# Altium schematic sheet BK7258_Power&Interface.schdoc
size 261 x 208 mm
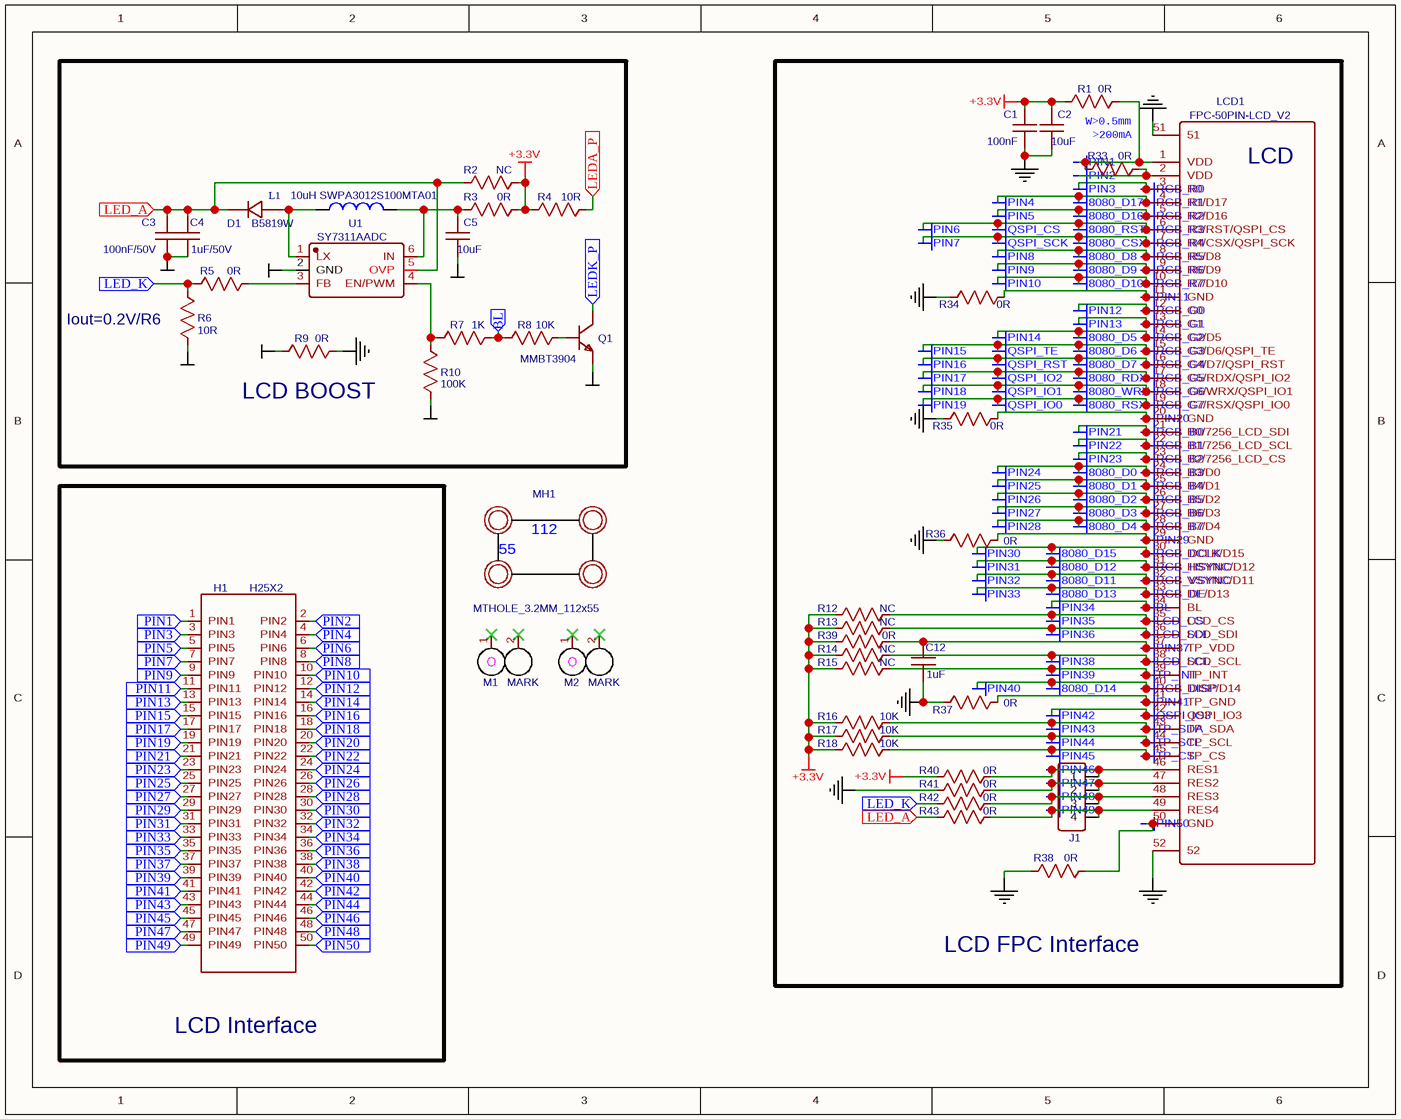
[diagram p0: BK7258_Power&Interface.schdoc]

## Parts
C1  100nF  [C0402]
C2  10uF  [C0603]
C3  100nF/50V  [C0603]
C4  1uF/50V  [C0603]
C5  10uF  [C0603]
C12  1uF  [C0402]
D1  B5819W  [SOD-123]
H1  H25X2  [H25X2]
J1  HDR-M-2.54_1x4  [HDR-M-2.54_1X4]  (value not drawn)
L1  10uH SWPA3012S100MTA01  [L3012]
LCD1  FPC-50PIN-LCD_V2  [FPC-SMD_AFC01-S50FCC-00_VERSA]
M1  MARK  [MARK]
M2  MARK  [MARK]
MH1  MTHOLE_3.2MM_112x55  [MTHOLE_3.2MM_112X55]
Q1  MMBT3904  [SOT-23]
R1  0R  [R0402]
R2  NC  [R0402]
R3  0R  [R0402]
R4  10R  [R0402]
R5  0R  [R0402]
R6  10R  [R0402]
R7  1K  [R0402]
R8  10K  [R0402]
R9  0R  [R0402]
R10  100K  [R0402]
R12  NC  [R0402]
R13  NC  [R0402]
R14  NC  [R0402]
R15  NC  [R0402]
R16  10K  [R0402]
R17  10K  [R0402]
R18  10K  [R0402]
R33  0R  [R0402]
R34  0R  [R0402]
R35  0R  [R0402]
R36  0R  [R0402]
R37  0R  [R0402]
R38  0R  [R0402]
R39  0R  [R0402]
R40  0R  [R0402]
R41  0R  [R0402]
R42  0R  [R0402]
R43  0R  [R0402]
U1  SY7311AADC  [TSOT-23-6_L2.9-W1.6-P0.95-LS2.8-BR]

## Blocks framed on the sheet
LCD BOOST: C3-C5 D1 L1 Q1 R2-R10 U1
LCD FPC Interface: C1 C2 C12 J1 LCD1 R1 R12-R18 R33-R43
LCD Interface: H1

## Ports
BL (in), LED_A (in), LED_K (in), LEDA_P (in), LEDK_P (in), PIN1 (in), PIN2 (in), PIN3 (in), PIN4 (in), PIN5 (in), PIN6 (in), PIN7 (in), PIN8 (in), PIN9 (in), PIN10 (in), PIN11 (in), PIN12 (in), PIN13 (in), PIN14 (in), PIN15 (in), PIN16 (in), PIN17 (in), PIN18 (in), PIN19 (in), PIN20 (in), PIN21 (in), PIN22 (in), PIN23 (in), PIN24 (in), PIN25 (in), PIN26 (in), PIN27 (in), PIN28 (in), PIN29 (in), PIN30 (in), PIN31 (in), PIN32 (in), PIN33 (in), PIN34 (in), PIN35 (in), PIN36 (in), PIN37 (in), PIN38 (in), PIN39 (in), PIN40 (in), PIN41 (in), PIN42 (in), PIN43 (in), PIN44 (in), PIN45 (in), PIN46 (in), PIN47 (in), PIN48 (in), PIN49 (in), PIN50 (in)

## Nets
+3.3V: C1.1 C2.1 R1.1 R2.2 R3.2 R4.1 R12.1 R13.1 R14.1 R15.1 R16.1 R17.1 R18.1 R39.1 R40.1
GGND: C1.2 C2.2 C12.2 LCD1.51 LCD1.52 R9.2 R34.1 R35.1 R36.1 R37.1 R38.1 R41.1
GND: C3.2 C4.2 C5.2 Q1.2(E) R6.1 R9.1 R10.1 U1.2(GND)
BL: R7.2 R8.1 ; port BL
LED_A: C3.1 C4.1 D1.1(K) R2.1 R43.1 U1.5(OVP) ; port LED_A
LED_K: R5.1 R6.2 R42.1 ; port LED_K
LEDA_P: R4.2 ; port LEDA_P
LEDK_P: Q1.3(C) ; port LEDK_P
PIN1: H1.1(PIN1) ; port PIN1
PIN2: H1.2(PIN2) ; port PIN2
PIN3: H1.3(PIN3) ; port PIN3
PIN4: H1.4(PIN4) ; port PIN4
PIN5: H1.5(PIN5) ; port PIN5
PIN6: H1.6(PIN6) ; port PIN6
PIN7: H1.7(PIN7) ; port PIN7
PIN8: H1.8(PIN8) ; port PIN8
PIN9: H1.9(PIN9) ; port PIN9
PIN10: H1.10(PIN10) ; port PIN10
PIN11: H1.11(PIN11) ; port PIN11
PIN12: H1.12(PIN12) ; port PIN12
PIN13: H1.13(PIN13) ; port PIN13
PIN14: H1.14(PIN14) ; port PIN14
PIN15: H1.15(PIN15) ; port PIN15
PIN16: H1.16(PIN16) ; port PIN16
PIN17: H1.17(PIN17) ; port PIN17
PIN18: H1.18(PIN18) ; port PIN18
PIN19: H1.19(PIN19) ; port PIN19
PIN20: H1.20(PIN20) ; port PIN20
PIN21: H1.21(PIN21) ; port PIN21
PIN22: H1.22(PIN22) ; port PIN22
PIN23: H1.23(PIN23) ; port PIN23
PIN24: H1.24(PIN24) ; port PIN24
PIN25: H1.25(PIN25) ; port PIN25
PIN26: H1.26(PIN26) ; port PIN26
PIN27: H1.27(PIN27) ; port PIN27
PIN28: H1.28(PIN28) ; port PIN28
PIN29: H1.29(PIN29) ; port PIN29
PIN30: H1.30(PIN30) ; port PIN30
PIN31: H1.31(PIN31) ; port PIN31
PIN32: H1.32(PIN32) ; port PIN32
PIN33: H1.33(PIN33) ; port PIN33
PIN34: H1.34(PIN34) ; port PIN34
PIN35: H1.35(PIN35) ; port PIN35
PIN36: H1.36(PIN36) ; port PIN36
PIN37: H1.37(PIN37) ; port PIN37
PIN38: H1.38(PIN38) ; port PIN38
PIN39: H1.39(PIN39) ; port PIN39
PIN40: H1.40(PIN40) ; port PIN40
PIN41: H1.41(PIN41) ; port PIN41
PIN42: H1.42(PIN42) ; port PIN42
PIN43: H1.43(PIN43) ; port PIN43
PIN44: H1.44(PIN44) ; port PIN44
PIN45: H1.45(PIN45) ; port PIN45
PIN46: H1.46(PIN46) ; port PIN46
PIN47: H1.47(PIN47) ; port PIN47
PIN48: H1.48(PIN48) ; port PIN48
PIN49: H1.49(PIN49) ; port PIN49
PIN50: H1.50(PIN50) ; port PIN50
NetC5_1: C5.1 L1.2 R3.1 U1.6(IN)
NetC12_1: C12.1 LCD1.37(TP_VDD) R39.2
NetD1_2: D1.2(A) L1.1 U1.1(LX)
NetJ1_1: J1.1 LCD1.46(RES1) R40.2
NetJ1_2: J1.2 LCD1.47(RES2) R41.2
NetJ1_3: J1.3 LCD1.48(RES3) R42.2
NetJ1_4: J1.4 LCD1.49(RES4) R43.2
NetLCD1_1: LCD1.1(VDD) R1.2 R33.1
NetLCD1_2: LCD1.2(VDD) R33.2
NetLCD1_11: LCD1.11(GND) R34.2
NetLCD1_20: LCD1.20(GND) R35.2
NetLCD1_29: LCD1.29(GND) R36.2
NetLCD1_35: LCD1.35(LCD_CS) R12.2
NetLCD1_36: LCD1.36(LCD_SDI) R13.2
NetLCD1_38: LCD1.38(LCD_SCL) R14.2
NetLCD1_39: LCD1.39(TP_INT) R15.2
NetLCD1_41: LCD1.41(TP_GND) R37.2
NetLCD1_43: LCD1.43(TP_SDA) R16.2
NetLCD1_44: LCD1.44(TP_SCL) R17.2
NetLCD1_45: LCD1.45(TP_CS) R18.2
NetLCD1_50: LCD1.50(GND) R38.2
NetQ1_1: Q1.1(B) R8.2
NetR5_2: R5.2 U1.3(FB)
NetR7_1: R7.1 R10.2 U1.4(EN/PWM)

Not connected (* = marked no-connect by the designer): LCD1 3(R0) 4(R1/D17) 5(R2/D16) 6(R3/RST/QSPI_CS) 7(R4/CSX/QSPI_SCK) 8(R5/D8) 9(R6/D9) 10(R7/D10) 12(G0) 13(G1) 14(G2/D5) 15(G3/D6/QSPI_TE) 16(G4/D7/QSPI_RST) 17(G5/RDX/QSPI_IO2) 18(G6/WRX/QSPI_IO1) 19(G7/RSX/QSPI_IO0) 21(B0/7256_LCD_SDI) 22(B1/7256_LCD_SCL) 23(B2/7256_LCD_CS) 24(B3/D0) 25(B4/D1) 26(B5/D2) 27(B6/D3) 28(B7/D4) 30(DCLK/D15) 31(HSYNC/D12) 32(VSYNC/D11) 33(DE/D13) 34(BL) 40(DISP/D14) 42(QSPI_IO3); M1 1* 2*; M2 1* 2*

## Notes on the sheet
- (near R1) W>0.5mm
- >200mA
- (near R6) Iout=0.2V/R6
- Labels drawn without touching a wire or pin: 8080_CSX, 8080_D0, 8080_D1, 8080_D2, 8080_D3, 8080_D4, 8080_D5, 8080_D6, 8080_D7, 8080_D8, 8080_D9, 8080_D10, 8080_D11, 8080_D12, 8080_D13, 8080_D14, 8080_D15, 8080_D16, 8080_D17, 8080_RDX, 8080_RST, 8080_RSX, 8080_WRX, BL, LCD_CS, LCD_SCL, LCD_SDI, PIN1, PIN2, PIN3, PIN4, PIN5, PIN6, PIN7, PIN8, PIN9, PIN10, PIN11, PIN12, PIN13, PIN14, PIN15, PIN16, PIN17, PIN18, PIN19, PIN20, PIN21, PIN22, PIN23, PIN24, PIN25, PIN26, PIN27, PIN28, PIN29, PIN30, PIN31, PIN32, PIN33, PIN34, PIN35, PIN36, PIN37, PIN38, PIN39, PIN40, PIN41, PIN42, PIN43, PIN44, PIN45, PIN46, PIN47, PIN48, PIN49, PIN50, QSPI_CS, QSPI_IO0, QSPI_IO1, QSPI_IO2, QSPI_IO3, QSPI_RST, QSPI_SCK, QSPI_TE, RGB_B0, RGB_B1, RGB_B2, RGB_B3, RGB_B4, RGB_B5, RGB_B6, RGB_B7, RGB_DCLK, RGB_DE, RGB_DISP, RGB_G0, RGB_G1, RGB_G2, RGB_G3, RGB_G4, RGB_G5, RGB_G6, RGB_G7, RGB_HSYNC, RGB_R0, RGB_R1, RGB_R2, RGB_R3, RGB_R4, RGB_R5, RGB_R6, RGB_R7, RGB_VSYNC, TP_CS, TP_INT, TP_SCL, TP_SDA

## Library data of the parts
C1 = 100nF: BOM_Manufacturer: Walsin(华新科); Manufacturer Part: 0402B104K160CT
C2 C5 = 10uF: BOM_Manufacturer: SAMSUNG(三星); Manufacturer Part: CL10A106MA8NRNC
C3 = 100nF/50V: Manufacturer Part: 0603B104K500NT; BOM_Manufacturer: FH(风华)
C4 = 1uF/50V: BOM_Manufacturer: SAMSUNG(三星); Manufacturer Part: CL10A105KB8NNNC
C12 = 1uF: Manufacturer Part: CL05A105KO5NNNC; BOM_Manufacturer: SAMSUNG(三星)
D1 = B5819W: BOM_Manufacturer: MDD; Contributor: LCSC
H1 = H25X2: Contributor: jian.shi1
J1 = HDR-M-2.54_1x4: Contributor: LCEDA_Lib
L1 = 10uH SWPA3012S100MTA01: BOM_Manufacturer: Sunlord（顺络）
LCD1 = FPC-50PIN-LCD_V2: BOM_Manufacturer Part: AFC01-S50FCC-00; BOM_Manufacturer: JS(钜硕电子); Contributor: qunshan.xu
M1 M2 = MARK: Contributor: jian.shi1
MH1 = MTHOLE_3.2MM_112x55: Contributor: qunshan.xu
Q1 = MMBT3904: BOM_Manufacturer: GOODWORK; Contributor: lcsc
R1 R3 R5 R9 R33-R43 = 0R: Manufacturer Part: 0402WGF0000TCE; BOM_Manufacturer: UNI-ROYAL(厚声); nameAlias: Value(Ω); Contributor: LCEDA_Lib
R2 = NC: Manufacturer Part: 0402WGF0000TCE; BOM_Manufacturer: UNI-ROYAL(厚声); nameAlias: Value(Ω); Contributor: LCEDA_Lib
R4 R6 = 10R: Manufacturer Part: CRCW040210R0FKED; BOM_Manufacturer: VISHAY(威世); nameAlias: Value(Ω); Contributor: LCEDA_Lib
R7 = 1K: Manufacturer Part: 0402WGF1001TCE; BOM_Manufacturer: UNI-ROYAL(厚声); nameAlias: Value(Ω); Contributor: LCEDA_Lib
R8 R16-R18 = 10K: Manufacturer Part: 0402WGF1002TCE; BOM_Manufacturer: UNI-ROYAL(厚声); nameAlias: Value(Ω); Contributor: LCEDA_Lib
R10 = 100K: Manufacturer Part: RC0402FR-07100KL; BOM_Manufacturer: YAGEO(国巨); nameAlias: Value(Ω); Contributor: LCEDA_Lib
R12-R15 = NC: Manufacturer Part: 0402WGF1002TCE; BOM_Manufacturer: UNI-ROYAL(厚声); nameAlias: Value(Ω); Contributor: LCEDA_Lib
U1 = SY7311AADC: BOM_Manufacturer: 矽力杰silergy; Contributor: lcsc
